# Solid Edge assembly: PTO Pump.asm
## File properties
Author: Dan
Template: Normal.asm
Last saved by: Dan
Revision: 305
Application: Solid Edge
ProtocolId (internal): P00050405154705720
Protocol (internal): P00050405154705720<@PID>[Object]<@EL>CADDescription=PTO Pump<@EL>Description=Assembly protocol<@EL>[GroupMan]<@EL>UseUserDescription=1<@EL>UserDescription=PTO Pump<@EL>[Acad]<@EL>ReallySmartPart=1<@EL>SmartPart=1<@EL>[View]<@EL>View=MODEL<@EL>Description=Parametric model<@EL>Data=(setq _data (list "0"))<@EL>Driver=C:/PROGRAM FILES/SOLID EDGE V16/HANDBOOK/DATA/DRV/USERPART.LSP<@EL>[Main]<@EL>DataFile=SpiData|asmpart<@EL>View=MODEL<@EL>[Globals]<@EL>Standard=ISO<@EL>PrfStd=ISO<@EL>Language=NO<@EL>Model=Asmpart<@EL>TypeOfPart=10<@EL>BOM1=<@EL>NormName=Assembly protocol<@EL>Caption=Assembly protocol<@EL>BOM2=<@EL>BOM3=<@EL>Path=C:\PROGRAM FILES\SOLID EDGE V16\HANDBOOK\DATA\<@EL>[Version]<@EL>Version=2.2<@EL>
Project Name: Piston Pump P52
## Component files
Shaft Ass.asm
M12-35.par
Piston.asm
Shaft Seal 35,52,7.par
Piston Spring.par
Inlet Housing.par
Oil Seal.par
M6-08.par
C W ID6-1.par
Housing.asm
2-043.par
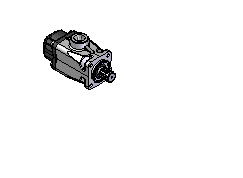
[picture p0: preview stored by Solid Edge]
